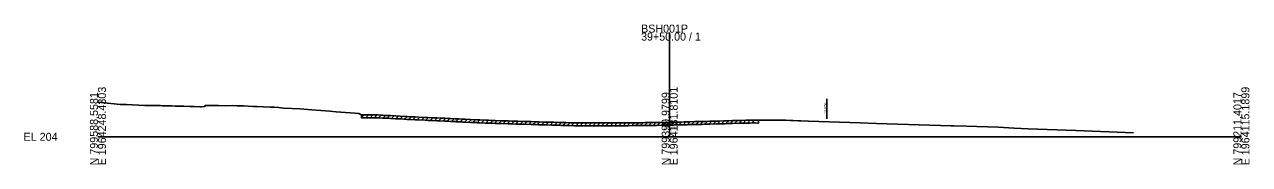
# Model space of a CAD drawing. Extents: x -26 to 1403, y -10 to 19587.
# Drawn here: x 974.3 to 1402.8, y 3490.3 to 3539.3 of the extents above; entities that cross this region are included whole.
import ezdxf

# ---------------------------------------------------------------- set-up
doc = ezdxf.new("R2010")
doc.units = 0
for name, color, linetype in [('Default', 7, 'Continuous'), ('RD_GPK_XS_Cell', 7, 'Continuous'), ('RD_XS_ExGround', 7, 'Continuous'), ('RD_XS_ExPaveRet', 7, 'Continuous'), ('RD_XS_ExRW', 7, 'Continuous'), ('RD_XS_TX_Elev_EX', 7, 'Continuous')]:
    doc.layers.add(name, color=color, linetype=linetype)

msp = doc.modelspace()

# ---------------------------------------------------------------- linework, layer by layer
at = {"layer": 'RD_GPK_XS_Cell'}
for p, q in [((1200, 3500), (1200, 3536.42)), ((1000, 3500), (1200, 3500)), ((1200, 3500), (1400, 3500))]:
    msp.add_line(p, q, dxfattribs=at)
at = {"layer": 'RD_XS_ExGround'}
msp.add_lwpolyline([(1000, 3512.14), (1007.87, 3511.27), (1009.97, 3511.23), (1016.46, 3510.96), (1017.22, 3510.95), (1019.02, 3510.91), (1019.93, 3510.91), (1021.91, 3510.88), (1022.52, 3510.86), (1023.87, 3510.83), (1024.38, 3510.82), (1025.86, 3510.8), (1026.98, 3510.76), (1029.62, 3510.69), (1030.09, 3510.67), (1032.2, 3510.61), (1033.62, 3510.56), (1035.63, 3510.47), (1036.18, 3510.47), (1037.35, 3510.53), (1037.51, 3510.97), (1038.29, 3510.96), (1042.16, 3510.91), (1044.46, 3510.87), (1047.01, 3510.88), (1048.75, 3510.85), (1050.1, 3510.81), (1051.01, 3510.77), (1054.16, 3510.64), (1055.54, 3510.57), (1060.2, 3510.41), (1061.63, 3510.32), (1063.24, 3510.2), (1064.96, 3510.06), (1070.67, 3509.76), (1074.85, 3509.41), (1081.08, 3508.91), (1083.38, 3508.7), (1089.92, 3508.23), (1091.3, 3508.16), (1092.18, 3507.68), (1097.76, 3507.62), (1098.64, 3507.58), (1099.54, 3507.53), (1100.52, 3507.49), (1101.08, 3507.46), (1102.32, 3507.4), (1104.1, 3507.31), (1105.67, 3507.22), (1108.19, 3507.08), (1109.09, 3507.02), (1109.49, 3507), (1110.99, 3506.93), (1112.09, 3506.87), (1114.44, 3506.76), (1115.43, 3506.72), (1117.03, 3506.65), (1118.63, 3506.58), (1119.69, 3506.53), (1121.33, 3506.45), (1122.35, 3506.41), (1123.34, 3506.37), (1124.98, 3506.29), (1125.29, 3506.28), (1126.19, 3506.24), (1127.25, 3506.18), (1127.65, 3506.16), (1128.46, 3506.12), (1130.31, 3506.04), (1132.55, 3505.94), (1132.94, 3505.92), (1133.64, 3505.89), (1135.57, 3505.81), (1136.64, 3505.77), (1138.25, 3505.71), (1139.01, 3505.68), (1141.19, 3505.6), (1143.55, 3505.53), (1144.83, 3505.5), (1146.21, 3505.46), (1146.86, 3505.44), (1148.95, 3505.38), (1151.5, 3505.3), (1153.02, 3505.26), (1154.15, 3505.22), (1156.18, 3505.15), (1156.81, 3505.14), (1158.61, 3505.09), (1159.45, 3505.07), (1161.22, 3505.02), (1162.11, 3505), (1162.53, 3504.99), (1163.69, 3504.96), (1164.76, 3504.93), (1166.65, 3504.87), (1167.51, 3504.86), (1169, 3504.82), (1169.6, 3504.82), (1170.59, 3504.83), (1171.86, 3504.83), (1172.37, 3504.83), (1174.32, 3504.83), (1175.38, 3504.84), (1176.97, 3504.85), (1177.72, 3504.85), (1179.88, 3504.87), (1182.25, 3504.87), (1183.56, 3504.87), (1184.89, 3504.87), (1185.53, 3504.87), (1187.64, 3504.89), (1190.18, 3504.92), (1191.4, 3504.94), (1192.85, 3504.96), (1194.81, 3504.99), (1195.5, 3505), (1197.29, 3505.02), (1198.19, 3505.03), (1199.29, 3505.04), (1200, 3505.06), (1200.84, 3505.07), (1201.26, 3505.09), (1202.44, 3505.12), (1203.49, 3505.15), (1205.16, 3505.2), (1206.13, 3505.23), (1207.11, 3505.26), (1208.8, 3505.3), (1209.89, 3505.32), (1211.42, 3505.35), (1212.26, 3505.37), (1214.08, 3505.42), (1216.34, 3505.48), (1216.7, 3505.49), (1217.29, 3505.51), (1218.8, 3505.56), (1219.36, 3505.58), (1220.47, 3505.6), (1222, 3505.64), (1224.82, 3505.7), (1226.67, 3505.75), (1227.3, 3505.77), (1227.95, 3505.79), (1229.49, 3505.84), (1229.95, 3505.84), (1230.86, 3505.81), (1232.69, 3505.82), (1235.29, 3505.79), (1236.48, 3505.79), (1237.93, 3505.79), (1239.91, 3505.78), (1240.59, 3505.77), (1242.32, 3505.71), (1243.2, 3505.68), (1244.95, 3505.6), (1245.87, 3505.55), (1248.6, 3505.48), (1266.65, 3504.89), (1272.39, 3504.65), (1298.42, 3503.81), (1298.73, 3503.8), (1299.31, 3503.79), (1303.67, 3503.67), (1314.89, 3503.41), (1320.48, 3503.04), (1325.43, 3502.78), (1342.14, 3502.17), (1362.31, 3501.43)], dxfattribs=at)
at = {"layer": 'RD_XS_ExPaveRet'}
for p, q in [((1092.18, 3506.68), (1092.18, 3507.68)), ((1092.18, 3506.68), (1093.17, 3507.67)), ((1092.18, 3506.68), (1097.76, 3506.62)), ((1093.68, 3506.66), (1094.67, 3507.65)), ((1095.18, 3506.65), (1096.17, 3507.64)), ((1096.68, 3506.63), (1097.67, 3507.62)), ((1097.76, 3506.62), (1098.64, 3506.58)), ((1098.18, 3506.6), (1099.13, 3507.56)), ((1098.64, 3506.58), (1099.54, 3506.53)), ((1099.54, 3506.53), (1100.52, 3506.49)), ((1099.68, 3506.53), (1100.63, 3507.48)), ((1100.52, 3506.49), (1101.08, 3506.46)), ((1101.08, 3506.46), (1102.32, 3506.4)), ((1101.18, 3506.46), (1102.13, 3507.41)), ((1102.32, 3506.4), (1104.1, 3506.31)), ((1102.68, 3506.38), (1103.63, 3507.33)), ((1104.1, 3506.31), (1105.67, 3506.22)), ((1104.18, 3506.3), (1105.12, 3507.25)), ((1105.67, 3506.22), (1108.19, 3506.08)), ((1105.68, 3506.22), (1106.62, 3507.16)), ((1107.18, 3506.13), (1108.12, 3507.08)), ((1108.19, 3506.08), (1109.09, 3506.02)), ((1108.68, 3506.05), (1109.62, 3506.99)), ((1109.09, 3506.02), (1109.49, 3506)), ((1109.49, 3506), (1110.99, 3505.93)), ((1110.18, 3505.96), (1111.13, 3506.92)), ((1110.99, 3505.93), (1112.09, 3505.87)), ((1111.68, 3505.89), (1112.63, 3506.85)), ((1112.09, 3505.87), (1114.44, 3505.76)), ((1113.18, 3505.82), (1114.13, 3506.77)), ((1114.44, 3505.76), (1115.43, 3505.72)), ((1114.68, 3505.75), (1115.64, 3506.71)), ((1115.43, 3505.72), (1117.03, 3505.65)), ((1116.18, 3505.68), (1117.14, 3506.64)), ((1117.03, 3505.65), (1118.63, 3505.58)), ((1117.68, 3505.62), (1118.64, 3506.58)), ((1118.63, 3505.58), (1119.69, 3505.53)), ((1119.18, 3505.56), (1120.13, 3506.51)), ((1119.69, 3505.53), (1121.33, 3505.45)), ((1120.68, 3505.49), (1121.63, 3506.44)), ((1121.33, 3505.45), (1122.35, 3505.41)), ((1122.18, 3505.42), (1123.14, 3506.38)), ((1122.35, 3505.41), (1123.34, 3505.37)), ((1123.68, 3505.36), (1124.63, 3506.31)), ((1125.18, 3505.29), (1126.13, 3506.24)), ((1126.68, 3505.21), (1127.63, 3506.16)), ((1128.18, 3505.13), (1129.13, 3506.09)), ((1129.68, 3505.07), (1130.63, 3506.02)), ((1131.18, 3505), (1132.13, 3505.96)), ((1132.68, 3504.93), (1133.63, 3505.89)), ((1134.18, 3504.87), (1135.14, 3505.83)), ((1135.68, 3504.81), (1136.63, 3505.77)), ((1137.18, 3504.75), (1138.14, 3505.71)), ((1138.68, 3504.69), (1139.64, 3505.66)), ((1140.18, 3504.64), (1141.14, 3505.6)), ((1141.68, 3504.58), (1142.65, 3505.56)), ((1143.18, 3504.54), (1144.15, 3505.52)), ((1144.68, 3504.5), (1145.65, 3505.48)), ((1146.18, 3504.47), (1147.15, 3505.44)), ((1213.68, 3504.41), (1214.7, 3505.43)), ((1215.18, 3504.45), (1216.21, 3505.48)), ((1216.68, 3504.49), (1217.71, 3505.52)), ((1218.18, 3504.54), (1219.21, 3505.57)), ((1219.68, 3504.59), (1220.7, 3505.61)), ((1221.18, 3504.62), (1222.2, 3505.64)), ((1222.68, 3504.65), (1223.7, 3505.68)), ((1224.18, 3504.69), (1225.2, 3505.71)), ((1225.68, 3504.73), (1226.7, 3505.75)), ((1227.18, 3504.76), (1228.21, 3505.8)), ((1228.68, 3504.81), (1229.7, 3505.84)), ((1231.07, 3505.81), (1231.07, 3504.81)), ((1123.34, 3505.37), (1124.98, 3505.29)), ((1124.98, 3505.29), (1125.29, 3505.28)), ((1125.29, 3505.28), (1126.19, 3505.24)), ((1126.19, 3505.24), (1127.25, 3505.18)), ((1127.25, 3505.18), (1127.65, 3505.16)), ((1127.65, 3505.16), (1128.46, 3505.12)), ((1128.46, 3505.12), (1130.31, 3505.04)), ((1130.31, 3505.04), (1132.55, 3504.94)), ((1132.55, 3504.94), (1132.94, 3504.92)), ((1132.94, 3504.92), (1133.64, 3504.89)), ((1133.64, 3504.89), (1135.57, 3504.81)), ((1135.57, 3504.81), (1136.64, 3504.77)), ((1136.64, 3504.77), (1138.25, 3504.71)), ((1138.25, 3504.71), (1139.01, 3504.68)), ((1139.01, 3504.68), (1141.19, 3504.6)), ((1141.19, 3504.6), (1143.55, 3504.53)), ((1143.55, 3504.53), (1144.83, 3504.5)), ((1144.83, 3504.5), (1146.21, 3504.46)), ((1146.21, 3504.46), (1146.86, 3504.44)), ((1146.86, 3504.44), (1148.95, 3504.38)), ((1147.68, 3504.42), (1148.65, 3505.39)), ((1148.95, 3504.38), (1151.5, 3504.3)), ((1149.18, 3504.37), (1150.15, 3505.34)), ((1150.68, 3504.32), (1151.65, 3505.29)), ((1151.5, 3504.3), (1153.02, 3504.26)), ((1152.18, 3504.28), (1153.15, 3505.25)), ((1153.02, 3504.26), (1154.15, 3504.22)), ((1153.68, 3504.24), (1154.65, 3505.21)), ((1154.15, 3504.22), (1156.18, 3504.15)), ((1155.18, 3504.19), (1156.14, 3505.16)), ((1156.18, 3504.15), (1156.81, 3504.14)), ((1156.68, 3504.14), (1157.65, 3505.12)), ((1156.81, 3504.14), (1158.61, 3504.09)), ((1158.18, 3504.1), (1159.15, 3505.08)), ((1158.61, 3504.09), (1159.45, 3504.07)), ((1159.45, 3504.07), (1161.22, 3504.02)), ((1159.68, 3504.06), (1160.65, 3505.04)), ((1161.18, 3504.03), (1162.15, 3505)), ((1161.22, 3504.02), (1162.11, 3504)), ((1162.11, 3504), (1162.53, 3503.99)), ((1162.53, 3503.99), (1163.69, 3503.96)), ((1162.68, 3503.99), (1163.65, 3504.96)), ((1163.69, 3503.96), (1164.76, 3503.93)), ((1164.18, 3503.95), (1165.15, 3504.92)), ((1164.76, 3503.93), (1166.65, 3503.87)), ((1165.68, 3503.9), (1166.65, 3504.87)), ((1166.65, 3503.87), (1167.51, 3503.86)), ((1167.18, 3503.86), (1168.16, 3504.84)), ((1167.51, 3503.86), (1169, 3503.82)), ((1168.68, 3503.83), (1169.67, 3504.82)), ((1169, 3503.82), (1169.6, 3503.82)), ((1169.6, 3503.82), (1170.59, 3503.83)), ((1170.18, 3503.83), (1171.18, 3504.83)), ((1170.59, 3503.83), (1171.86, 3503.83)), ((1171.68, 3503.83), (1172.68, 3504.83)), ((1171.86, 3503.83), (1172.37, 3503.83)), ((1172.37, 3503.83), (1174.32, 3503.83)), ((1173.18, 3503.83), (1174.18, 3504.83)), ((1174.32, 3503.83), (1175.38, 3503.84)), ((1174.68, 3503.84), (1175.68, 3504.84)), ((1175.38, 3503.84), (1176.97, 3503.85)), ((1176.18, 3503.84), (1177.18, 3504.85)), ((1176.97, 3503.85), (1177.72, 3503.85)), ((1177.68, 3503.85), (1178.68, 3504.86)), ((1177.72, 3503.85), (1179.88, 3503.87)), ((1179.18, 3503.86), (1180.18, 3504.87)), ((1179.88, 3503.87), (1182.25, 3503.87)), ((1180.68, 3503.87), (1181.68, 3504.87)), ((1182.18, 3503.87), (1183.18, 3504.87)), ((1182.25, 3503.87), (1183.56, 3503.87)), ((1183.56, 3503.87), (1184.89, 3503.87)), ((1183.68, 3503.87), (1184.67, 3504.87)), ((1184.89, 3503.87), (1185.53, 3503.87)), ((1185.18, 3503.87), (1186.19, 3504.88)), ((1185.53, 3503.87), (1187.64, 3503.89)), ((1186.68, 3503.88), (1187.69, 3504.89)), ((1187.64, 3503.89), (1190.18, 3503.92)), ((1188.18, 3503.9), (1189.19, 3504.91)), ((1189.68, 3503.92), (1190.69, 3504.93)), ((1190.18, 3503.92), (1191.4, 3503.94)), ((1191.18, 3503.93), (1192.19, 3504.95)), ((1191.4, 3503.94), (1192.85, 3503.96)), ((1192.68, 3503.96), (1193.69, 3504.97)), ((1192.85, 3503.96), (1194.81, 3503.99)), ((1194.18, 3503.98), (1195.19, 3505)), ((1194.81, 3503.99), (1195.5, 3504)), ((1195.5, 3504), (1197.29, 3504.02)), ((1195.68, 3504), (1196.69, 3505.01)), ((1197.18, 3504.02), (1198.19, 3505.03)), ((1197.29, 3504.02), (1198.19, 3504.03)), ((1198.19, 3504.03), (1199.29, 3504.04)), ((1198.68, 3504.04), (1199.69, 3505.05)), ((1199.29, 3504.04), (1200, 3504.06)), ((1200, 3504.06), (1200.84, 3504.07)), ((1200.18, 3504.06), (1201.2, 3505.08)), ((1200.84, 3504.07), (1201.26, 3504.09)), ((1201.26, 3504.09), (1202.44, 3504.12)), ((1201.68, 3504.1), (1202.71, 3505.13)), ((1202.44, 3504.12), (1203.49, 3504.15)), ((1203.18, 3504.14), (1204.21, 3505.17)), ((1203.49, 3504.15), (1205.16, 3504.2)), ((1204.68, 3504.19), (1205.71, 3505.22)), ((1205.16, 3504.2), (1206.13, 3504.23)), ((1206.13, 3504.23), (1207.11, 3504.26)), ((1206.18, 3504.23), (1207.21, 3505.26)), ((1207.11, 3504.26), (1208.8, 3504.3)), ((1207.68, 3504.28), (1208.7, 3505.3)), ((1208.8, 3504.3), (1209.89, 3504.32)), ((1209.18, 3504.31), (1210.19, 3505.33)), ((1209.89, 3504.32), (1211.42, 3504.35)), ((1210.68, 3504.34), (1211.7, 3505.36)), ((1211.42, 3504.35), (1212.26, 3504.37)), ((1212.18, 3504.37), (1213.2, 3505.4)), ((1212.26, 3504.37), (1214.08, 3504.42)), ((1214.08, 3504.42), (1216.34, 3504.48)), ((1216.34, 3504.48), (1216.7, 3504.49)), ((1216.7, 3504.49), (1217.29, 3504.51)), ((1217.29, 3504.51), (1218.8, 3504.56)), ((1218.8, 3504.56), (1219.36, 3504.58)), ((1219.36, 3504.58), (1220.47, 3504.6)), ((1220.47, 3504.6), (1222, 3504.64)), ((1222, 3504.64), (1224.82, 3504.7)), ((1224.82, 3504.7), (1226.67, 3504.75)), ((1226.67, 3504.75), (1227.3, 3504.77)), ((1227.3, 3504.77), (1227.95, 3504.79)), ((1227.95, 3504.79), (1229.49, 3504.84)), ((1229.49, 3504.84), (1229.95, 3504.84)), ((1229.95, 3504.84), (1230.86, 3504.81)), ((1230.86, 3504.81), (1231.07, 3504.81))]:
    msp.add_line(p, q, dxfattribs=at)
at = {"layer": 'RD_XS_ExRW'}
msp.add_line((1254.98, 3506.27), (1254.98, 3513.27), dxfattribs=at)

# ---------------------------------------------------------------- texts
at = {"layer": 'Default'}
msp.add_text('-', height=0.0001, dxfattribs=at).set_placement((1000, 3500))
at = {"layer": 'RD_GPK_XS_Cell'}
for s, p in [('39+50.00 / 1', (1190, 3533.62)), ('BSH001P', (1190, 3536.42)), ('EL 204', (974, 3498.6))]:
    msp.add_text(s, height=2.8, dxfattribs=at).set_placement(p)
for s, p in [('N 799588.5581', (1000, 3490)), ('E 1964248.4303', (1002.8, 3490)), ('N 799399.9799', (1200, 3490)), ('E 1964181.8101', (1202.8, 3490)), ('N 799211.4017', (1400, 3490)), ('E 1964115.1899', (1402.8, 3490))]:
    msp.add_text(s, height=2.8, rotation=90, dxfattribs=at).set_placement(p)
at = {"layer": 'RD_XS_ExRW'}
msp.add_text('EX. R/W ', height=0.75, rotation=90, dxfattribs=at).set_placement((1254.73, 3507.94))
at = {"layer": 'RD_XS_TX_Elev_EX'}
msp.add_text('209.06', height=1, dxfattribs=at).set_placement((1197.95, 3502.56))

doc.saveas('drawing.dxf')
